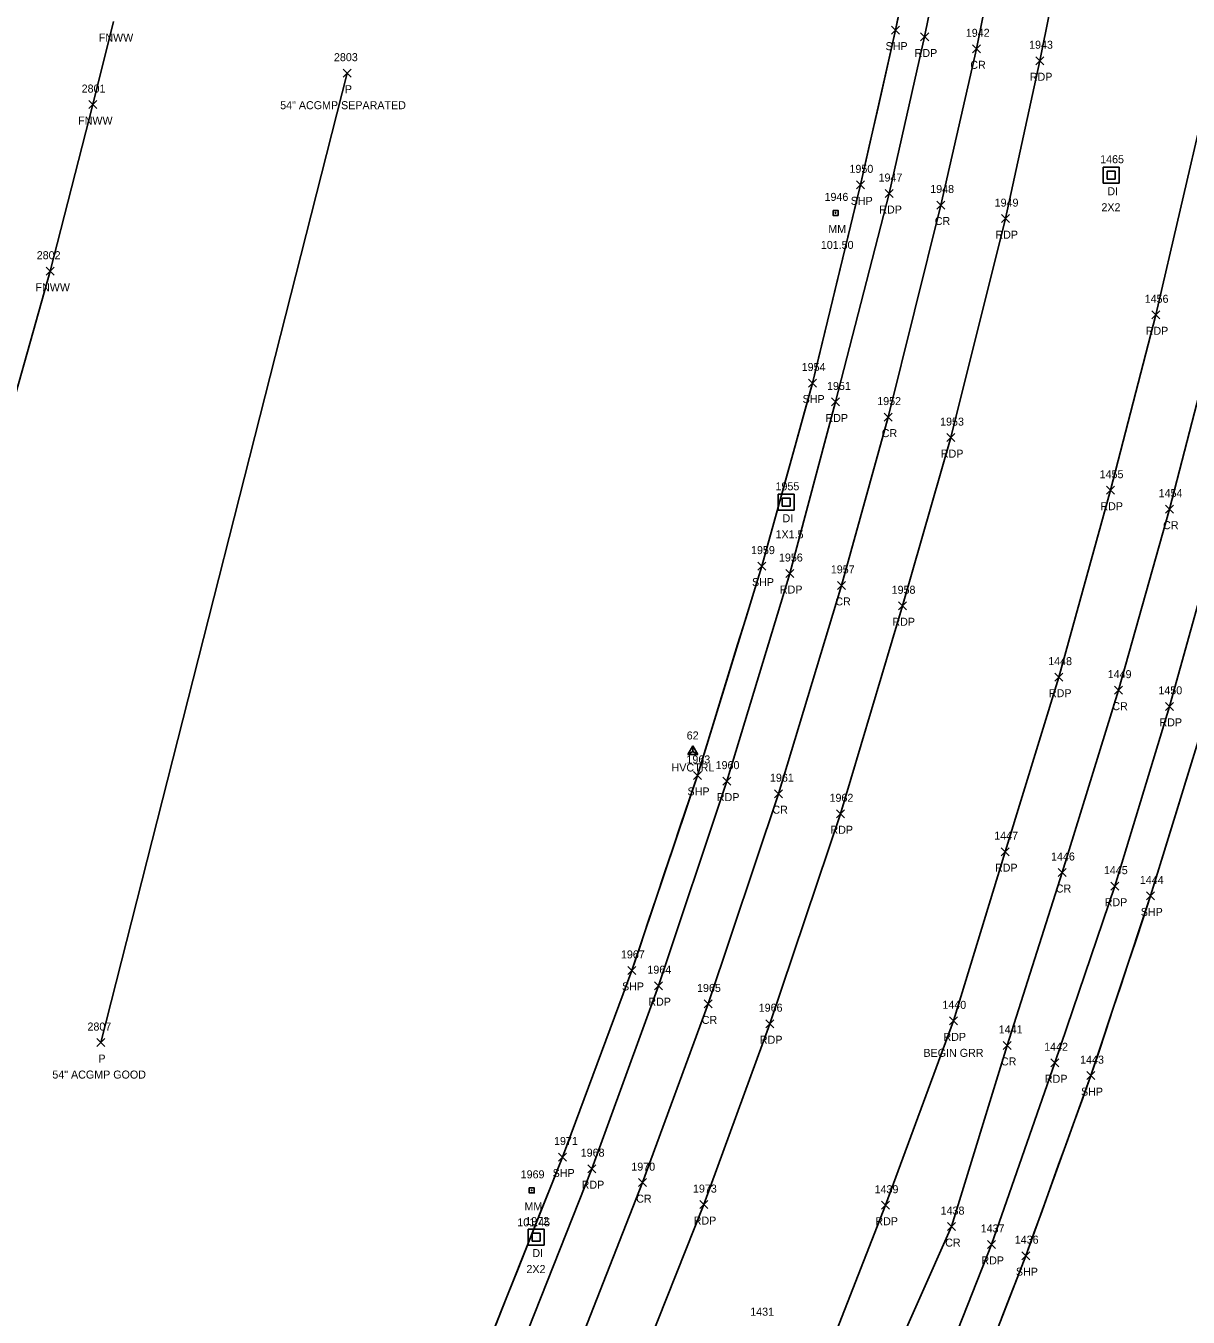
# Model space of a CAD drawing. Extents: x 1472022 to 1479249, y 777216 to 786527.
# Drawn here: x 1473285.6 to 1473576.1, y 778752 to 779074.7 of the extents above; entities that cross this region are included whole.
import ezdxf

# ---------------------------------------------------------------- set-up
doc = ezdxf.new("R2010")
doc.units = 0
for name, color, linetype in [('C_A', 7, 'Continuous'), ('C_I', 7, 'Continuous'), ('CPSM', 7, 'Continuous'), ('D_A', 7, 'Continuous'), ('D_C', 7, 'Continuous'), ('D_I', 7, 'Continuous'), ('D_TIC', 7, 'Continuous'), ('DCP', 7, 'Continuous'), ('DS', 7, 'Continuous'), ('L_A', 7, 'Continuous'), ('L_I', 7, 'Continuous'), ('L_TIC', 7, 'Continuous'), ('LFNC', 7, 'Continuous'), ('LSOGP', 7, 'Continuous'), ('P_A', 7, 'Continuous'), ('P_C', 7, 'Continuous'), ('P_I', 7, 'Continuous'), ('P_TIC', 7, 'Continuous'), ('PET', 7, 'Continuous'), ('PRC', 7, 'Continuous'), ('PSP', 7, 'Continuous'), ('S_A', 7, 'Continuous'), ('S_C', 7, 'Continuous'), ('S_I', 7, 'Continuous'), ('SRM', 7, 'Continuous')]:
    doc.layers.add(name, color=color, linetype=linetype)

msp = doc.modelspace()

# ---------------------------------------------------------------- linework, layer by layer
at = {"layer": 'CPSM'}
for p, q in [((1473451.05, 778892.64), (1473452.3, 778894.8)), ((1473453.55, 778892.64), (1473452.3, 778894.8)), ((1473452.3, 778893.36), (1473452.3, 778894.8)), ((1473451.05, 778892.64), (1473452.3, 778893.36)), ((1473451.05, 778892.64), (1473453.55, 778892.64)), ((1473452.3, 778893.36), (1473452.3, 778893.36)), ((1473452.3, 778893.36), (1473453.55, 778892.64))]:
    msp.add_line(p, q, dxfattribs=at)
at = {"layer": 'D_TIC'}
for points in [[(1473364.98, 779061.86), (1473366.98, 779063.86)], [(1473366.98, 779061.86), (1473364.98, 779063.86)], [(1473303.39, 778819.62), (1473305.39, 778821.62)], [(1473305.39, 778819.62), (1473303.39, 778821.62)]]:
    msp.add_lwpolyline(points, dxfattribs=at)
at = {"layer": 'DCP'}
msp.add_lwpolyline([(1473365.98, 779062.86), (1473304.39, 778820.62)], dxfattribs=at)
at = {"layer": 'DS'}
for p, q in [((1473554.84, 779039.36), (1473558.84, 779039.36)), ((1473554.84, 779035.36), (1473554.84, 779039.36)), ((1473555.84, 779036.36), (1473555.84, 779038.36)), ((1473555.84, 779038.36), (1473557.84, 779038.36)), ((1473556.85, 779037.36), (1473556.85, 779037.36)), ((1473556.85, 779037.36), (1473556.85, 779037.36)), ((1473557.84, 779038.36), (1473557.84, 779036.36)), ((1473558.84, 779039.36), (1473558.84, 779035.36)), ((1473558.84, 779035.36), (1473554.84, 779035.36)), ((1473557.84, 779036.36), (1473555.84, 779036.36)), ((1473473.66, 778957.62), (1473477.66, 778957.62)), ((1473473.66, 778953.62), (1473473.66, 778957.62)), ((1473474.66, 778954.62), (1473474.66, 778956.62)), ((1473474.66, 778956.62), (1473476.66, 778956.62)), ((1473476.66, 778956.62), (1473476.66, 778954.62)), ((1473477.66, 778957.62), (1473477.66, 778953.62)), ((1473477.66, 778953.62), (1473473.66, 778953.62)), ((1473476.66, 778954.62), (1473474.66, 778954.62)), ((1473475.67, 778955.63), (1473475.67, 778955.63)), ((1473475.67, 778955.63), (1473475.67, 778955.63)), ((1473411.16, 778774.02), (1473415.16, 778774.02)), ((1473411.16, 778770.02), (1473411.16, 778774.02)), ((1473412.16, 778771.02), (1473412.16, 778773.02)), ((1473412.16, 778773.02), (1473414.16, 778773.02)), ((1473413.16, 778772.02), (1473413.16, 778772.02)), ((1473413.16, 778772.02), (1473413.16, 778772.02)), ((1473414.16, 778773.02), (1473414.16, 778771.02)), ((1473415.16, 778774.02), (1473415.16, 778770.02)), ((1473415.16, 778770.02), (1473411.16, 778770.02)), ((1473414.16, 778771.02), (1473412.16, 778771.02))]:
    msp.add_line(p, q, dxfattribs=at)
at = {"layer": 'L_TIC'}
for points in [[(1473301.37, 779054.02), (1473303.37, 779056.02)], [(1473303.37, 779054.02), (1473301.37, 779056.02)], [(1473290.71, 779012.38), (1473292.71, 779014.38)], [(1473292.71, 779012.38), (1473290.71, 779014.38)]]:
    msp.add_lwpolyline(points, dxfattribs=at)
at = {"layer": 'LFNC'}
msp.add_lwpolyline([(1473307.53, 779075.77), (1473302.37, 779055.02), (1473291.71, 779013.38), (1473278.06, 778965.07), (1473248.41, 778925.8), (1473203.34, 778863.73), (1473186.54, 778833.93), (1473159.66, 778785.12), (1473137.27, 778746.63), (1473131.18, 778719.11), (1473124.89, 778691.16), (1473117.49, 778666.71), (1473112.14, 778636.96), (1473112.13, 778637.02), (1473099.55, 778583.54), (1473097.59, 778571.13), (1473104.16, 778540.32), (1473121.35, 778447.02)], dxfattribs=at)
at = {"layer": 'LSOGP'}
for points in [[(1473504.24, 779079.76), (1473502.95, 779073.62), (1473500.77, 779063.95), (1473498.59, 779054.29), (1473496.42, 779044.62), (1473494.24, 779034.96), (1473492.74, 779028.77), (1473491.23, 779022.57), (1473489.73, 779016.38), (1473488.23, 779010.19), (1473486.72, 779004), (1473485.22, 778997.81), (1473483.71, 778991.62), (1473482.21, 778985.43), (1473480.63, 778979.71), (1473479.05, 778973.99), (1473477.47, 778968.27), (1473475.89, 778962.55), (1473474.31, 778956.83), (1473472.72, 778951.11), (1473471.14, 778945.4), (1473469.56, 778939.68), (1473467.55, 778933.14), (1473465.54, 778926.6), (1473463.52, 778920.06), (1473461.51, 778913.53), (1473459.5, 778906.99), (1473457.48, 778900.45), (1473455.47, 778893.91), (1473453.46, 778887.37), (1473451.41, 778881.28), (1473449.36, 778875.19), (1473447.32, 778869.1), (1473445.27, 778863.01), (1473443.23, 778856.92), (1473441.18, 778850.83), (1473439.14, 778844.74), (1473437.09, 778838.65), (1473434.92, 778832.82), (1473432.76, 778826.99), (1473430.59, 778821.17), (1473428.42, 778815.34), (1473426.26, 778809.51), (1473424.09, 778803.68), (1473421.92, 778797.85), (1473419.76, 778792.02), (1473416.98, 778785.04), (1473414.2, 778778.05), (1473411.42, 778771.06), (1473408.64, 778764.08), (1473405.86, 778757.09), (1473403.08, 778750.1)], [(1473529.53, 778751.88), (1473531.53, 778757.04), (1473533.52, 778762.2), (1473535.51, 778767.36), (1473537.55, 778772.98), (1473539.58, 778778.61), (1473541.62, 778784.23), (1473543.65, 778789.86), (1473545.69, 778795.48), (1473547.72, 778801.1), (1473549.75, 778806.73), (1473551.79, 778812.35), (1473553.65, 778817.97), (1473555.52, 778823.58), (1473557.38, 778829.19), (1473559.25, 778834.81), (1473561.11, 778840.42), (1473562.98, 778846.04), (1473564.85, 778851.65), (1473566.71, 778857.26), (1473568.46, 778862.94), (1473570.2, 778868.62), (1473571.95, 778874.3), (1473573.7, 778879.97), (1473575.44, 778885.65), (1473577.19, 778891.33)]]:
    msp.add_lwpolyline(points, dxfattribs=at)
at = {"layer": 'P_TIC'}
for points in [[(1473501.95, 779072.62), (1473503.95, 779074.62)], [(1473503.95, 779072.62), (1473501.95, 779074.62)], [(1473509.25, 779070.91), (1473511.25, 779072.91)], [(1473511.25, 779070.91), (1473509.25, 779072.91)], [(1473522.22, 779067.95), (1473524.22, 779069.95)], [(1473524.22, 779067.95), (1473522.22, 779069.95)], [(1473538.05, 779064.97), (1473540.05, 779066.97)], [(1473540.05, 779064.97), (1473538.05, 779066.97)], [(1473493.24, 779033.96), (1473495.24, 779035.96)], [(1473495.24, 779033.96), (1473493.24, 779035.96)], [(1473500.42, 779031.79), (1473502.42, 779033.79)], [(1473502.42, 779031.79), (1473500.42, 779033.79)], [(1473513.33, 779028.92), (1473515.33, 779030.92)], [(1473515.33, 779028.92), (1473513.33, 779030.92)], [(1473529.44, 779025.51), (1473531.44, 779027.51)], [(1473531.44, 779025.51), (1473529.44, 779027.51)], [(1473566.98, 779001.48), (1473568.98, 779003.48)], [(1473568.98, 779001.48), (1473566.98, 779003.48)], [(1473481.21, 778984.43), (1473483.21, 778986.43)], [(1473483.21, 778984.43), (1473481.21, 778986.43)], [(1473486.97, 778979.7), (1473488.97, 778981.7)], [(1473488.97, 778979.7), (1473486.97, 778981.7)], [(1473500.09, 778975.92), (1473502.09, 778977.92)], [(1473502.09, 778975.92), (1473500.09, 778977.92)], [(1473515.8, 778970.79), (1473517.8, 778972.79)], [(1473517.8, 778970.79), (1473515.8, 778972.79)], [(1473555.66, 778957.65), (1473557.66, 778959.65)], [(1473557.66, 778957.65), (1473555.66, 778959.65)], [(1473570.41, 778952.91), (1473572.41, 778954.91)], [(1473572.41, 778952.91), (1473570.41, 778954.91)], [(1473468.56, 778938.68), (1473470.56, 778940.68)], [(1473470.56, 778938.68), (1473468.56, 778940.68)], [(1473475.59, 778936.83), (1473477.59, 778938.83)], [(1473477.59, 778936.83), (1473475.59, 778938.83)], [(1473488.49, 778933.86), (1473490.49, 778935.86)], [(1473490.49, 778933.86), (1473488.49, 778935.86)], [(1473503.7, 778928.77), (1473505.7, 778930.77)], [(1473505.7, 778928.77), (1473503.7, 778930.77)], [(1473542.81, 778910.93), (1473544.81, 778912.93)], [(1473544.81, 778910.93), (1473542.81, 778912.93)], [(1473557.69, 778907.68), (1473559.69, 778909.68)], [(1473559.69, 778907.68), (1473557.69, 778909.68)], [(1473570.44, 778903.64), (1473572.44, 778905.64)], [(1473572.44, 778903.64), (1473570.44, 778905.64)], [(1473452.46, 778886.37), (1473454.46, 778888.37)], [(1473454.46, 778886.37), (1473452.46, 778888.37)], [(1473459.83, 778884.95), (1473461.83, 778886.95)], [(1473461.83, 778884.95), (1473459.83, 778886.95)], [(1473472.76, 778881.81), (1473474.76, 778883.81)], [(1473474.76, 778881.81), (1473472.76, 778883.81)], [(1473488.22, 778876.79), (1473490.22, 778878.79)], [(1473490.22, 778876.79), (1473488.22, 778878.79)], [(1473529.33, 778867.32), (1473531.33, 778869.32)], [(1473531.33, 778867.32), (1473529.33, 778869.32)], [(1473543.58, 778862.11), (1473545.58, 778864.11)], [(1473545.58, 778862.11), (1473543.58, 778864.11)], [(1473556.74, 778858.7), (1473558.74, 778860.7)], [(1473558.74, 778858.7), (1473556.74, 778860.7)], [(1473565.71, 778856.26), (1473567.71, 778858.26)], [(1473567.71, 778856.26), (1473565.71, 778858.26)], [(1473436.09, 778837.65), (1473438.09, 778839.65)], [(1473438.09, 778837.65), (1473436.09, 778839.65)], [(1473442.7, 778833.83), (1473444.7, 778835.83)], [(1473444.7, 778833.83), (1473442.7, 778835.83)], [(1473455.11, 778829.27), (1473457.11, 778831.27)], [(1473457.11, 778829.27), (1473455.11, 778831.27)], [(1473516.46, 778825.05), (1473518.46, 778827.05)], [(1473518.46, 778825.05), (1473516.46, 778827.05)], [(1473470.58, 778824.33), (1473472.58, 778826.33)], [(1473472.58, 778824.33), (1473470.58, 778826.33)], [(1473529.88, 778818.91), (1473531.88, 778820.91)], [(1473531.88, 778818.91), (1473529.88, 778820.91)], [(1473541.8, 778814.57), (1473543.8, 778816.57)], [(1473543.8, 778814.57), (1473541.8, 778816.57)], [(1473550.79, 778811.35), (1473552.79, 778813.35)], [(1473552.79, 778811.35), (1473550.79, 778813.35)], [(1473418.76, 778791.02), (1473420.76, 778793.02)], [(1473420.76, 778791.02), (1473418.76, 778793.02)], [(1473426.04, 778788.1), (1473428.04, 778790.1)], [(1473428.04, 778788.1), (1473426.04, 778790.1)], [(1473438.73, 778784.61), (1473440.73, 778786.61)], [(1473440.73, 778784.61), (1473438.73, 778786.61)], [(1473454.05, 778779.13), (1473456.05, 778781.13)], [(1473456.05, 778779.13), (1473454.05, 778781.13)], [(1473499.45, 778778.97), (1473501.45, 778780.97)], [(1473501.45, 778778.97), (1473499.45, 778780.97)], [(1473515.94, 778773.63), (1473517.94, 778775.63)], [(1473517.94, 778773.63), (1473515.94, 778775.63)], [(1473525.94, 778769.17), (1473527.94, 778771.17)], [(1473527.94, 778769.17), (1473525.94, 778771.17)], [(1473534.51, 778766.36), (1473536.51, 778768.36)], [(1473536.51, 778766.36), (1473534.51, 778768.36)]]:
    msp.add_lwpolyline(points, dxfattribs=at)
at = {"layer": 'PET'}
for points in [[(1473559.55, 779345.54), (1473562.13, 779344.85), (1473559.08, 779325.48), (1473547.78, 779268.19), (1473538.56, 779219.47), (1473529.75, 779172.07), (1473520.23, 779121.16), (1473510.25, 779071.91), (1473501.42, 779032.79), (1473487.97, 778980.7), (1473476.59, 778937.83), (1473460.83, 778885.95), (1473443.7, 778834.83), (1473427.04, 778789.1), (1473404.79, 778732.7), (1473383.99, 778685.53), (1473360.34, 778636.02), (1473337.25, 778590.82), (1473309.69, 778539.48), (1473284.14, 778496.13), (1473255.52, 778449.63), (1473221.14, 778399.57)], [(1473562.13, 779344.85), (1473573.79, 779342.6), (1473588.74, 779339.91), (1473585.78, 779323.26), (1473585.84, 779321.4), (1473576.73, 779269.38), (1473567.96, 779217.59), (1473558.64, 779166.28), (1473549.3, 779116.91), (1473539.05, 779065.97), (1473530.44, 779026.51), (1473516.8, 778971.79), (1473504.7, 778929.77), (1473489.22, 778877.79), (1473471.58, 778825.33), (1473455.05, 778780.13), (1473432.04, 778722.28), (1473410.95, 778674.71), (1473387.24, 778624.16), (1473365.27, 778580.65), (1473335.21, 778525.25), (1473309.35, 778481.56), (1473280.39, 778434.36), (1473245.89, 778383.45)], [(1473301.45, 778389.87), (1473329.64, 778433.49), (1473354.46, 778474.65), (1473376.14, 778512.49), (1473401.99, 778560.39), (1473423.89, 778603.83), (1473444.72, 778647.26), (1473465.48, 778692.86), (1473485.43, 778741.59), (1473500.45, 778779.97), (1473517.46, 778826.05), (1473530.33, 778868.32), (1473543.81, 778911.93), (1473556.66, 778958.65), (1473567.98, 779002.48), (1473580.14, 779054.81), (1473589.43, 779101.31), (1473598.46, 779148.03), (1473608.13, 779200.81), (1473618, 779253.28), (1473624.21, 779286.68), (1473629.11, 779313.19), (1473632.64, 779331.64)], [(1473351.95, 778416.72), (1473378.27, 778459.7), (1473399.26, 778496.93), (1473426.04, 778546.24), (1473448.78, 778590.55), (1473469.94, 778634.62), (1473491.01, 778680.96), (1473511.23, 778730.25), (1473526.94, 778770.17), (1473542.8, 778815.57), (1473557.74, 778859.7), (1473571.44, 778904.64), (1473584.34, 778950.97), (1473595.35, 778994.87), (1473607.13, 779045.13), (1473617.39, 779095.53), (1473626.97, 779145.31), (1473636.44, 779196.8), (1473646.17, 779249.15), (1473652.07, 779281.25), (1473656.8, 779307.9), (1473660.32, 779326.69), (1473648.23, 779328.95), (1473632.64, 779331.64)]]:
    msp.add_lwpolyline(points, dxfattribs=at)
at = {"layer": 'PRC'}
for points in [[(1473573.79, 779342.6), (1473570.41, 779324.08), (1473560.67, 779266.03), (1473551.92, 779218.05), (1473542.92, 779169.19), (1473533.33, 779119.74), (1473523.22, 779068.95), (1473514.33, 779029.92), (1473501.09, 778976.92), (1473489.49, 778934.86), (1473473.76, 778882.81), (1473456.11, 778830.27), (1473439.73, 778785.61), (1473416.92, 778727.46), (1473396.04, 778680.67), (1473372.49, 778630.75), (1473349.26, 778585.34), (1473321.1, 778533.63), (1473295.37, 778489.48), (1473266.55, 778442.63), (1473232.46, 778392.44)], [(1473340.44, 778424.05), (1473366.77, 778467.15), (1473388.27, 778504.09), (1473415.13, 778552.7), (1473437.21, 778597.16), (1473457.95, 778640.21), (1473479.17, 778687.02), (1473500.17, 778736.74), (1473516.94, 778774.63), (1473530.88, 778819.91), (1473544.58, 778863.11), (1473558.69, 778908.68), (1473571.41, 778953.91), (1473582.65, 778997.42), (1473594.11, 779047.2), (1473604.41, 779097.99), (1473613.95, 779144.11), (1473624.22, 779197.73), (1473633.15, 779249.53), (1473640.4, 779286.65), (1473645.03, 779310.08), (1473648.23, 779328.95)]]:
    msp.add_lwpolyline(points, dxfattribs=at)
at = {"layer": 'PSP'}
for points in [[(1473559.55, 779345.54), (1473556.55, 779328.39), (1473555.66, 779326.52), (1473543.65, 779268.7), (1473533.24, 779220.88), (1473523.59, 779172.64), (1473513.3, 779122.79), (1473502.95, 779073.62), (1473494.24, 779034.96), (1473482.21, 778985.43), (1473469.56, 778939.68), (1473453.46, 778887.37), (1473437.09, 778838.65), (1473419.76, 778792.02), (1473397.52, 778736.13), (1473377.14, 778688.43), (1473353.45, 778638.67), (1473330.09, 778593.76), (1473303, 778543.94), (1473277.25, 778499.77), (1473248.4, 778453.47), (1473214.72, 778403.13)], [(1473360.11, 778411.57), (1473386.71, 778454.12), (1473408.21, 778491.8), (1473436.32, 778544.11), (1473456.83, 778585.94), (1473478.34, 778630.94), (1473498.91, 778676.33), (1473519.57, 778726.08), (1473535.51, 778767.36), (1473551.79, 778812.35), (1473566.71, 778857.26), (1473580.68, 778902.68), (1473593.4, 778949.04), (1473604.43, 778993.44), (1473615.75, 779042.5), (1473626.64, 779093.98), (1473636.29, 779143.66), (1473644.06, 779195.83), (1473651.7, 779249.18), (1473655.52, 779279.56), (1473658.83, 779307.84), (1473662.07, 779326.37), (1473660.32, 779326.69)]]:
    msp.add_lwpolyline(points, dxfattribs=at)
at = {"layer": 'SRM'}
for points in [[(1473487.36, 779028.58), (1473488.61, 779028.58), (1473488.61, 779027.33), (1473487.36, 779027.33)], [(1473411.42, 778784.31), (1473412.67, 778784.31), (1473412.67, 778783.06), (1473411.42, 778783.06)]]:
    msp.add_lwpolyline(points, close=True, dxfattribs=at)
for centre in [(1473487.98, 779027.95), (1473412.05, 778783.69)]:
    msp.add_circle(centre, 0.0833, dxfattribs=at)

# ---------------------------------------------------------------- texts
at = {"layer": 'C_A'}
msp.add_text('HVCTRL', height=2, dxfattribs=at).set_placement((1473446.99, 778888.36))
at = {"layer": 'C_I'}
msp.add_text('62', height=2, dxfattribs=at).set_placement((1473450.79, 778896.36))
at = {"layer": 'D_A'}
for s, p in [('P', (1473365.36, 779057.86)), ('DI', (1473555.9, 779032.36)), ('DI', (1473474.72, 778950.63)), ('P', (1473303.77, 778815.62)), ('DI', (1473412.22, 778767.02))]:
    msp.add_text(s, height=2, dxfattribs=at).set_placement(p)
at = {"layer": 'D_C'}
for s, p in [('54" ACGMP SEPARATED', (1473349.2, 779053.86)), ('2X2', (1473554.42, 779028.36)), ('1X1.5', (1473472.99, 778946.63)), ('54" ACGMP GOOD', (1473292.27, 778811.62)), ('2X2', (1473410.74, 778763.02))]:
    msp.add_text(s, height=2, dxfattribs=at).set_placement(p)
at = {"layer": 'D_I'}
for s, p in [('2803', (1473362.64, 779065.86)), ('1465', (1473554.11, 779040.36)), ('1955', (1473472.98, 778958.63)), ('2807', (1473301.05, 778823.62)), ('1972', (1473410.47, 778775.02)), ('1431', (1473466.66, 778752.36))]:
    msp.add_text(s, height=2, dxfattribs=at).set_placement(p)
at = {"layer": 'L_A'}
for p in [(1473303.87, 779070.77), (1473298.71, 779050.02), (1473288.06, 779008.38)]:
    msp.add_text('FNWW', height=2, dxfattribs=at).set_placement(p)
at = {"layer": 'L_I'}
for s, p in [('2801', (1473299.59, 779058.02)), ('2802', (1473288.37, 779016.38))]:
    msp.add_text(s, height=2, dxfattribs=at).set_placement(p)
at = {"layer": 'P_A'}
for s, p in [('SHP', (1473500.48, 779068.62)), ('RDP', (1473507.74, 779066.91)), ('CR', (1473521.65, 779063.95)), ('RDP', (1473536.53, 779060.97)), ('SHP', (1473491.78, 779029.96)), ('RDP', (1473498.91, 779027.79)), ('CR', (1473512.77, 779024.92)), ('RDP', (1473527.93, 779021.51)), ('RDP', (1473565.47, 778997.48)), ('SHP', (1473479.75, 778980.43)), ('RDP', (1473485.46, 778975.7)), ('CR', (1473499.52, 778971.92)), ('RDP', (1473514.29, 778966.79)), ('RDP', (1473554.15, 778953.65)), ('CR', (1473569.84, 778948.91)), ('SHP', (1473467.1, 778934.68)), ('RDP', (1473474.07, 778932.83)), ('CR', (1473487.92, 778929.86)), ('RDP', (1473502.19, 778924.77)), ('RDP', (1473541.3, 778906.93)), ('CR', (1473557.13, 778903.68)), ('RDP', (1473568.93, 778899.64)), ('SHP', (1473450.99, 778882.37)), ('RDP', (1473458.32, 778880.95)), ('CR', (1473472.2, 778877.81)), ('RDP', (1473486.71, 778872.79)), ('RDP', (1473527.82, 778863.32)), ('CR', (1473543.02, 778858.11)), ('RDP', (1473555.23, 778854.7)), ('SHP', (1473564.25, 778852.26)), ('SHP', (1473434.62, 778833.65)), ('RDP', (1473441.19, 778829.83)), ('CR', (1473454.54, 778825.27)), ('RDP', (1473469.07, 778820.33)), ('RDP', (1473514.95, 778821.05)), ('CR', (1473529.31, 778814.91)), ('RDP', (1473540.29, 778810.57)), ('SHP', (1473549.32, 778807.35)), ('SHP', (1473417.29, 778787.02)), ('RDP', (1473424.53, 778784.1)), ('CR', (1473438.16, 778780.61)), ('RDP', (1473452.53, 778775.13)), ('RDP', (1473497.93, 778774.97)), ('CR', (1473515.38, 778769.63)), ('RDP', (1473524.43, 778765.17)), ('SHP', (1473533.05, 778762.36))]:
    msp.add_text(s, height=2, dxfattribs=at).set_placement(p)
at = {"layer": 'P_C'}
msp.add_text('BEGIN GRR', height=2, dxfattribs=at).set_placement((1473509.94, 778817.05))
at = {"layer": 'P_I'}
for s, p in [('1942', (1473520.53, 779071.95)), ('1943', (1473536.35, 779068.97)), ('1950', (1473491.46, 779037.96)), ('1947', (1473498.73, 779035.79)), ('1948', (1473511.64, 779032.92)), ('1949', (1473527.74, 779029.51)), ('1456', (1473565.23, 779005.48)), ('1954', (1473479.52, 778988.43)), ('1951', (1473485.85, 778983.7)), ('1952', (1473498.39, 778979.92)), ('1953', (1473514.11, 778974.79)), ('1455', (1473553.97, 778961.65)), ('1454', (1473568.72, 778956.91)), ('1959', (1473466.86, 778942.68)), ('1956', (1473473.84, 778940.83)), ('1957', (1473486.8, 778937.86)), ('1958', (1473502, 778932.77)), ('1448', (1473541.12, 778914.93)), ('1449', (1473555.99, 778911.68)), ('1450', (1473568.66, 778907.64)), ('1963', (1473450.72, 778890.37)), ('1960', (1473458.01, 778888.95)), ('1961', (1473471.59, 778885.81)), ('1962', (1473486.48, 778880.79)), ('1447', (1473527.64, 778871.32)), ('1446', (1473541.83, 778866.11)), ('1445', (1473555.04, 778862.7)), ('1444', (1473564.02, 778860.26)), ('1967', (1473434.35, 778841.65)), ('1964', (1473440.96, 778837.83)), ('1965', (1473453.37, 778833.27)), ('1966', (1473468.78, 778828.33)), ('1440', (1473514.68, 778829.05)), ('1441', (1473528.75, 778822.91)), ('1442', (1473540.11, 778818.57)), ('1443', (1473549.1, 778815.35)), ('1971', (1473417.63, 778795.02)), ('1968', (1473424.3, 778792.1)), ('1970', (1473436.95, 778788.61)), ('1973', (1473452.35, 778783.13)), ('1439', (1473497.74, 778782.97)), ('1438', (1473514.25, 778777.63)), ('1437', (1473524.25, 778773.17)), ('1436', (1473532.77, 778770.36))]:
    msp.add_text(s, height=2, dxfattribs=at).set_placement(p)
at = {"layer": 'S_A'}
for p in [(1473486.17, 779022.95), (1473410.24, 778778.69)]:
    msp.add_text('MM', height=2, dxfattribs=at).set_placement(p)
at = {"layer": 'S_C'}
for s, p in [('101.50', (1473484.3, 779018.95)), ('101.45', (1473408.46, 778774.69))]:
    msp.add_text(s, height=2, dxfattribs=at).set_placement(p)
at = {"layer": 'S_I'}
for s, p in [('1946', (1473485.23, 779030.95)), ('1969', (1473409.3, 778786.69))]:
    msp.add_text(s, height=2, dxfattribs=at).set_placement(p)

doc.saveas('drawing.dxf')
